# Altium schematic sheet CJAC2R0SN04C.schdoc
size 127 x 101 mm
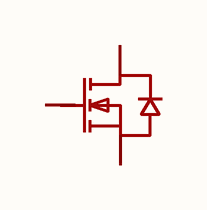
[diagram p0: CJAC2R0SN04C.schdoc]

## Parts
Q?  cjac2r0sn04c  [PDFNWB-8L_L6.0-W5.0-P1.27-BL-EP]  (value not drawn)

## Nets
NetQ?_1: Q?.1(S) Q?.2(S) Q?.3(S)
NetQ?_5: Q?.5(D) Q?.6(D) Q?.7(D) Q?.8(D)

Not connected (* = marked no-connect by the designer): Q? 4(G)

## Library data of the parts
Q? = cjac2r0sn04c: 数量:1个N沟道;漏源电压(Vdss):40V;连续漏极电流(Id):150A;导通电阻(RDS(on)):3.6mΩ@4.5V;耗散功率(Pd):96W;阈值电压(Vgs(th)):2.5V;; Manufacturer: CJ(江苏长电/长晶); AddInBom: yes; ModelId: e3e175b3db6c4f90a9ad9ca232f97958; ModelName: POWERVDFN-8_L6.0-W5.0-H1.0-P1.27; ModelTransform: 207.878,240.157,0,0,0,0,0,0,0; Number: 1个N沟道; Drain to Source Voltage: 40V; Current - Continuous Drain(Id): 150A; Pd - Power Dissipation: 96W; Gate Threshold Voltage (Vgs(th)): 2.5V; Gate Charge(Qg): 42.8nC@10V; Input Capacitance(Ciss): 3.06nF; Reverse Transfer Capacitance (Crss@Vds): 52pF; Type: N沟道; Output Capacitance(Coss): 900pF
